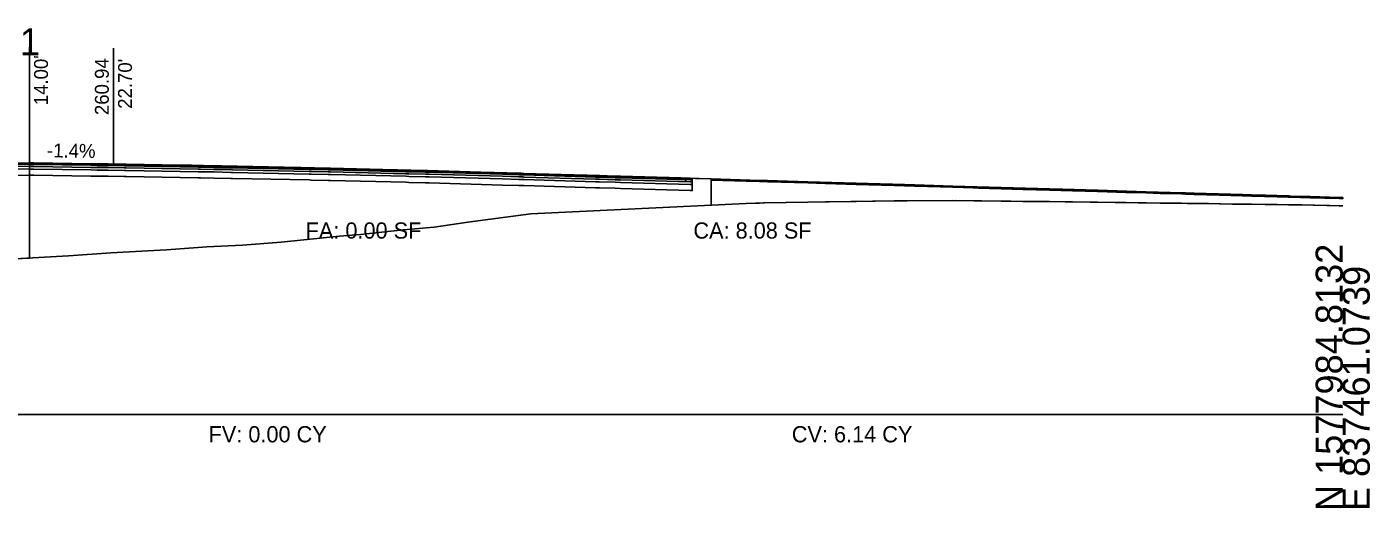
# Model space of a CAD drawing. Extents: x -26 to 6303, y -16 to 9563.
# Drawn here: x 2163.7 to 2302.8, y 3490.3 to 3540.1 of the extents above; entities that cross this region are included whole.
import ezdxf

# ---------------------------------------------------------------- set-up
doc = ezdxf.new("R2010")
doc.units = 0
for name, color, linetype in [('ASPHALT_19MM1', 7, 'Continuous'), ('ASPHALT_9_5MM1', 7, 'Continuous'), ('CONST_DCH', 7, 'Continuous'), ('CONST_LV3', 7, 'Continuous'), ('Default', 7, 'Continuous'), ('DTM_P_FINISHED_GRADE', 7, 'Continuous'), ('DTM_P_FINISHED_GRADE2', 7, 'Continuous'), ('DTM_X_GROUND', 7, 'Continuous'), ('TRANS_EOP_PAVED', 7, 'Continuous'), ('TRANS_PAVED_SHOULDERS', 7, 'Continuous'), ('XS_CELL', 7, 'Continuous'), ('XS_M_SHAPES_EARTHWORK', 7, 'Continuous'), ('XS_P_ASPHALT', 7, 'Continuous'), ('XS_P_GROUND', 7, 'Continuous'), ('XS_P_SUBGRADE_GRANULAR', 7, 'Continuous'), ('XS_P_SUBGRADE_LEVELING', 7, 'Continuous'), ('XS_P_SUBGRADE_MILLING', 7, 'Continuous'), ('XS_P_TX_CLEARZONE', 7, 'Continuous'), ('XS_P_TX_FS_BS', 7, 'Continuous'), ('XS_SHEET_EW_TX_AREA', 7, 'Continuous'), ('XS_SHEET_EW_TX_VOLUME', 7, 'Continuous')]:
    doc.layers.add(name, color=color, linetype=linetype)

msp = doc.modelspace()

# ---------------------------------------------------------------- linework, layer by layer
at = {"layer": 'ASPHALT_19MM1'}
for points in [[(2136, 3524.77), (2136, 3524.67), (2140.93, 3524.81), (2150, 3525.06), (2154.93, 3525.2), (2164, 3525.46), (2164, 3525.55), (2164, 3525.73), (2154.93, 3525.47), (2150, 3525.34), (2140.93, 3525.08), (2136, 3524.94), (2136, 3524.77)], [(2181.71, 3525.42), (2183.08, 3525.39), (2184.87, 3525.36), (2185.03, 3525.35), (2192.97, 3525.18), (2193.17, 3525.18), (2194.93, 3525.14), (2195.18, 3525.13), (2202.98, 3524.94), (2203.28, 3524.93), (2205.01, 3524.89), (2205.38, 3524.88), (2212.99, 3524.67), (2214.67, 3524.62), (2215.11, 3524.61), (2215.2, 3524.6), (2222.62, 3524.39), (2223.02, 3524.37), (2224.66, 3524.32), (2225.22, 3524.31), (2232.44, 3524.09), (2232.64, 3524.09), (2232.64, 3523.82), (2232.44, 3523.82), (2225.22, 3524.04), (2224.66, 3524.05), (2223.02, 3524.1), (2222.62, 3524.11), (2215.2, 3524.33), (2215.11, 3524.34), (2214.67, 3524.35), (2212.99, 3524.4), (2205.38, 3524.61), (2205.01, 3524.62), (2203.28, 3524.66), (2202.98, 3524.67), (2195.18, 3524.86), (2194.93, 3524.87), (2193.17, 3524.91), (2192.97, 3524.91), (2185.03, 3525.08), (2184.87, 3525.08), (2183.08, 3525.12), (2181.71, 3525.14), (2181.6, 3525.15), (2181.58, 3525.15), (2181.57, 3525.15), (2181.46, 3525.15), (2174.01, 3525.28), (2173.88, 3525.28), (2173.82, 3525.28), (2172.16, 3525.3), (2171.88, 3525.31), (2171.74, 3525.31), (2171.01, 3525.32), (2170.35, 3525.33), (2164.45, 3525.41), (2164.42, 3525.41), (2164, 3525.42), (2164, 3525.69), (2164.42, 3525.68), (2164.45, 3525.68), (2170.35, 3525.6), (2171.01, 3525.59), (2171.74, 3525.58), (2171.88, 3525.58), (2172.16, 3525.57), (2173.82, 3525.55), (2173.88, 3525.55), (2174.01, 3525.55), (2181.46, 3525.42), (2181.57, 3525.42), (2181.58, 3525.42), (2181.6, 3525.42), (2181.71, 3525.42)]]:
    msp.add_lwpolyline(points, dxfattribs=at)
at = {"layer": 'ASPHALT_9_5MM1'}
for points in [[(2136, 3525.2), (2136, 3525.15), (2140.93, 3525.29), (2150, 3525.54), (2154.93, 3525.68), (2164, 3525.94), (2164, 3525.98), (2164, 3526.06), (2154.93, 3525.81), (2150, 3525.67), (2140.93, 3525.41), (2136, 3525.28), (2136, 3525.2)], [(2181.71, 3525.75), (2183.08, 3525.72), (2184.87, 3525.69), (2185.03, 3525.68), (2192.97, 3525.52), (2193.17, 3525.51), (2194.93, 3525.47), (2195.18, 3525.47), (2202.98, 3525.28), (2203.28, 3525.27), (2205.01, 3525.23), (2205.38, 3525.21), (2212.99, 3525), (2214.67, 3524.95), (2215.11, 3524.94), (2215.2, 3524.94), (2222.62, 3524.72), (2223.02, 3524.71), (2224.66, 3524.66), (2225.22, 3524.64), (2232.44, 3524.43), (2232.64, 3524.42), (2232.64, 3524.3), (2232.44, 3524.3), (2225.22, 3524.51), (2224.66, 3524.53), (2223.02, 3524.58), (2222.62, 3524.59), (2215.2, 3524.81), (2215.11, 3524.82), (2214.67, 3524.83), (2212.99, 3524.88), (2205.38, 3525.09), (2205.01, 3525.1), (2203.28, 3525.14), (2202.98, 3525.15), (2195.18, 3525.34), (2194.93, 3525.35), (2193.17, 3525.39), (2192.97, 3525.39), (2185.03, 3525.56), (2184.87, 3525.56), (2183.08, 3525.6), (2181.71, 3525.62), (2181.6, 3525.63), (2181.58, 3525.63), (2181.57, 3525.63), (2181.46, 3525.63), (2174.01, 3525.76), (2173.88, 3525.76), (2173.82, 3525.76), (2172.16, 3525.78), (2171.88, 3525.79), (2171.74, 3525.79), (2171.01, 3525.8), (2170.35, 3525.81), (2164.45, 3525.89), (2164.42, 3525.89), (2164, 3525.9), (2164, 3526.02), (2164.42, 3526.02), (2164.45, 3526.01), (2170.35, 3525.93), (2171.01, 3525.92), (2171.74, 3525.91), (2171.88, 3525.91), (2172.16, 3525.91), (2173.82, 3525.88), (2173.88, 3525.88), (2174.01, 3525.88), (2181.46, 3525.75), (2181.57, 3525.75), (2181.58, 3525.75), (2181.6, 3525.75), (2181.71, 3525.75)]]:
    msp.add_lwpolyline(points, dxfattribs=at)
at = {"layer": 'CONST_LV3'}
for points in [[(2172.7, 3525.94), (2165.84, 3526.03), (2164, 3526.06), (2161.2, 3525.98), (2150, 3525.67)], [(2181.71, 3525.79), (2183.08, 3525.76), (2184.87, 3525.73), (2185.03, 3525.72), (2192.97, 3525.56), (2193.17, 3525.55), (2194.93, 3525.52), (2195.18, 3525.51), (2202.98, 3525.32), (2203.28, 3525.31), (2205.01, 3525.27), (2205.38, 3525.25), (2212.99, 3525.04), (2214.67, 3525), (2215.11, 3524.98), (2215.2, 3524.98), (2222.62, 3524.76), (2223.02, 3524.75), (2224.66, 3524.7), (2225.22, 3524.68), (2232.44, 3524.47), (2232.64, 3524.46), (2232.64, 3523.19), (2232.44, 3523.2), (2225.22, 3523.41), (2224.66, 3523.43), (2223.02, 3523.47), (2222.62, 3523.49), (2215.2, 3523.71), (2215.11, 3523.71), (2214.67, 3523.72), (2212.99, 3523.77), (2205.38, 3523.98), (2205.01, 3523.99), (2203.28, 3524.04), (2202.98, 3524.05), (2195.18, 3524.24), (2194.93, 3524.24), (2193.17, 3524.28), (2192.97, 3524.29), (2185.03, 3524.45), (2184.87, 3524.46), (2183.08, 3524.49), (2181.71, 3524.52), (2181.6, 3524.52), (2181.58, 3524.52), (2181.57, 3524.52), (2181.46, 3524.52), (2174.01, 3524.65), (2173.88, 3524.65), (2173.82, 3524.65), (2172.16, 3524.68), (2171.88, 3524.68), (2171.74, 3524.68), (2171.01, 3524.69), (2170.35, 3524.7), (2164.45, 3524.78), (2164.42, 3524.78), (2164, 3524.79), (2164, 3526.06), (2164.42, 3526.06), (2164.45, 3526.06), (2170.35, 3525.97), (2171.01, 3525.96), (2171.74, 3525.95), (2171.88, 3525.95), (2172.16, 3525.95), (2173.82, 3525.92), (2173.88, 3525.92), (2174.01, 3525.92), (2181.46, 3525.79), (2181.57, 3525.79), (2181.58, 3525.79), (2181.6, 3525.79), (2181.71, 3525.79)], [(2289.63, 3522.78), (2284.63, 3522.92), (2279.63, 3523.07), (2274.63, 3523.22), (2269.62, 3523.37), (2264.62, 3523.52), (2259.62, 3523.66), (2254.62, 3523.81), (2249.61, 3523.96), (2244.61, 3524.11), (2239.61, 3524.25), (2234.61, 3524.4), (2233.35, 3524.44), (2232.93, 3524.45)]]:
    msp.add_lwpolyline(points, dxfattribs=at)
at = {"layer": 'Default'}
msp.add_lwpolyline([(2172.7, 3525.94), (2173.84, 3525.92), (2173.9, 3525.92), (2174.02, 3525.92), (2178.59, 3525.84), (2180.56, 3525.81), (2180.66, 3525.81), (2180.67, 3525.81), (2180.77, 3525.81), (2183.3, 3525.76), (2183.88, 3525.75), (2190.38, 3525.61), (2192.04, 3525.58), (2192.13, 3525.57), (2194.93, 3525.52), (2194.93, 3525.52), (2194.96, 3525.51), (2194.98, 3525.51), (2195.07, 3525.51), (2195.18, 3525.51), (2201.95, 3525.34), (2201.99, 3525.34), (2202.02, 3525.34), (2202.13, 3525.34), (2204.88, 3525.27), (2205, 3525.27), (2205.01, 3525.27), (2205.05, 3525.26), (2205.1, 3525.26), (2205.23, 3525.26), (2211.85, 3525.07), (2211.99, 3525.07), (2211.99, 3525.07), (2211.99, 3525.07), (2212.03, 3525.07), (2212.03, 3525.07), (2212.07, 3525.07), (2212.11, 3525.07), (2214.79, 3524.99), (2214.91, 3524.99), (2215.11, 3524.98), (2215.11, 3524.98), (2215.2, 3524.98), (2221.65, 3524.79), (2221.67, 3524.79), (2221.69, 3524.79), (2221.77, 3524.78), (2222.05, 3524.77), (2222.05, 3524.77), (2224.66, 3524.7), (2224.74, 3524.69), (2224.83, 3524.69), (2225.02, 3524.69), (2225.21, 3524.68), (2231.49, 3524.5), (2231.49, 3524.5), (2231.5, 3524.5), (2231.7, 3524.49), (2232.04, 3524.13)], dxfattribs=at)
at = {"layer": 'DTM_P_FINISHED_GRADE'}
msp.add_lwpolyline([(2164, 3526.06), (2164.42, 3526.06), (2164.45, 3526.06), (2170.35, 3525.97), (2171.01, 3525.96), (2171.74, 3525.95), (2171.88, 3525.95), (2172.16, 3525.95), (2173.82, 3525.92), (2173.88, 3525.92), (2174.01, 3525.92), (2181.46, 3525.79), (2181.57, 3525.79), (2181.58, 3525.79), (2181.6, 3525.79), (2181.71, 3525.79), (2183.08, 3525.76), (2184.87, 3525.73), (2185.03, 3525.72), (2192.97, 3525.56), (2193.17, 3525.55), (2194.93, 3525.52), (2195.18, 3525.51), (2202.98, 3525.32), (2203.28, 3525.31), (2205.01, 3525.27), (2205.38, 3525.25), (2212.99, 3525.04), (2214.67, 3525), (2215.11, 3524.98), (2215.2, 3524.98), (2222.62, 3524.76), (2223.02, 3524.75), (2224.66, 3524.7), (2225.22, 3524.68), (2232.44, 3524.47), (2232.64, 3524.46)], dxfattribs=at)
at = {"layer": 'DTM_P_FINISHED_GRADE2'}
msp.add_lwpolyline([(2160.54, 3525.96), (2164, 3526.06), (2164.42, 3526.06), (2164.45, 3526.06), (2170.35, 3525.97), (2171.01, 3525.96), (2171.88, 3525.95), (2172.16, 3525.95), (2173.82, 3525.92), (2173.88, 3525.92), (2174.01, 3525.92), (2181.46, 3525.79), (2181.58, 3525.79), (2181.6, 3525.79), (2181.71, 3525.79), (2183.08, 3525.76), (2184.87, 3525.73), (2185.03, 3525.72), (2192.97, 3525.56), (2193.17, 3525.55), (2194.93, 3525.52), (2195.18, 3525.51), (2202.98, 3525.32), (2203.28, 3525.31), (2205.01, 3525.27), (2205.38, 3525.25), (2212.99, 3525.04), (2213.03, 3525.04), (2214.71, 3524.99), (2215.11, 3524.98), (2215.2, 3524.98), (2222.62, 3524.76), (2223.02, 3524.75), (2224.66, 3524.7), (2225.22, 3524.68), (2225.92, 3524.66), (2233.04, 3524.45), (2234.61, 3524.4), (2235.37, 3524.38), (2239.61, 3524.25), (2240.44, 3524.23), (2244.61, 3524.11), (2245.52, 3524.08), (2249.61, 3523.96), (2250.6, 3523.93), (2254.62, 3523.81), (2255.69, 3523.78), (2259.62, 3523.66), (2260.78, 3523.63), (2264.62, 3523.52), (2265.88, 3523.48), (2269.62, 3523.37), (2270.99, 3523.33), (2274.62, 3523.22), (2274.62, 3523.22), (2274.63, 3523.22), (2276.11, 3523.18), (2279.63, 3523.07), (2280.8, 3523.04), (2283.31, 3522.96), (2283.74, 3522.95), (2284.63, 3522.92), (2286.38, 3522.87), (2289.63, 3522.78), (2289.97, 3522.77), (2290.57, 3522.75), (2292.02, 3522.71), (2294.38, 3522.64), (2294.48, 3522.63), (2294.63, 3522.63), (2296.64, 3522.57), (2299.64, 3522.48), (2300, 3522.47)], dxfattribs=at)
at = {"layer": 'DTM_X_GROUND'}
msp.add_lwpolyline([(2162.49, 3516.12), (2168.04, 3516.42), (2172.43, 3516.75), (2178.19, 3517.05), (2182.37, 3517.36), (2186.08, 3517.55), (2190.07, 3517.85), (2196.11, 3518.47), (2198.27, 3518.66), (2202.7, 3519.12), (2205.91, 3519.4), (2209.4, 3519.91), (2215.91, 3520.79), (2238.24, 3521.84), (2240.11, 3521.93), (2253.55, 3522.12), (2259.91, 3522.18), (2262.13, 3522.14), (2262.59, 3522.13), (2268.67, 3522.06), (2276.42, 3521.97), (2278.81, 3521.93), (2286.11, 3521.84), (2288.57, 3521.8), (2295.32, 3521.72), (2298.64, 3521.64), (2300, 3521.61)], dxfattribs=at)
at = {"layer": 'TRANS_PAVED_SHOULDERS'}
for points in [[(2136, 3525.02), (2136, 3524.94), (2140.93, 3525.08), (2150, 3525.34), (2154.93, 3525.47), (2164, 3525.73), (2164, 3525.8), (2164, 3525.94), (2154.93, 3525.68), (2150, 3525.54), (2140.93, 3525.29), (2136, 3525.15), (2136, 3525.02)], [(2181.71, 3525.62), (2183.08, 3525.6), (2184.87, 3525.56), (2185.03, 3525.56), (2192.97, 3525.39), (2193.17, 3525.39), (2194.93, 3525.35), (2195.18, 3525.34), (2202.98, 3525.15), (2203.28, 3525.14), (2205.01, 3525.1), (2205.38, 3525.09), (2212.99, 3524.88), (2214.67, 3524.83), (2215.11, 3524.82), (2215.2, 3524.81), (2222.62, 3524.59), (2223.02, 3524.58), (2224.66, 3524.53), (2225.22, 3524.51), (2232.44, 3524.3), (2232.64, 3524.3), (2232.64, 3524.09), (2232.44, 3524.09), (2225.22, 3524.31), (2224.66, 3524.32), (2223.02, 3524.37), (2222.62, 3524.39), (2215.2, 3524.6), (2215.11, 3524.61), (2214.67, 3524.62), (2212.99, 3524.67), (2205.38, 3524.88), (2205.01, 3524.89), (2203.28, 3524.93), (2202.98, 3524.94), (2195.18, 3525.13), (2194.93, 3525.14), (2193.17, 3525.18), (2192.97, 3525.18), (2185.03, 3525.35), (2184.87, 3525.36), (2183.08, 3525.39), (2181.71, 3525.42), (2181.6, 3525.42), (2181.58, 3525.42), (2181.57, 3525.42), (2181.46, 3525.42), (2174.01, 3525.55), (2173.88, 3525.55), (2173.82, 3525.55), (2172.16, 3525.57), (2171.88, 3525.58), (2171.74, 3525.58), (2171.01, 3525.59), (2170.35, 3525.6), (2164.45, 3525.68), (2164.42, 3525.68), (2164, 3525.69), (2164, 3525.9), (2164.42, 3525.89), (2164.45, 3525.89), (2170.35, 3525.81), (2171.01, 3525.8), (2171.74, 3525.79), (2171.88, 3525.79), (2172.16, 3525.78), (2173.82, 3525.76), (2173.88, 3525.76), (2174.01, 3525.76), (2181.46, 3525.63), (2181.57, 3525.63), (2181.58, 3525.63), (2181.6, 3525.63), (2181.71, 3525.62)]]:
    msp.add_lwpolyline(points, dxfattribs=at)
at = {"layer": 'XS_CELL'}
msp.add_line((2150, 3500), (2300, 3500), dxfattribs=at)
at = {"layer": 'XS_M_SHAPES_EARTHWORK'}
msp.add_lwpolyline([(2162.49, 3516.12), (2164, 3516.2), (2164, 3525.46), (2154.93, 3525.2)], dxfattribs=at)
at = {"layer": 'XS_P_ASPHALT'}
for points in [[(2164, 3526.06), (2164.42, 3526.06), (2164.45, 3526.06), (2170.35, 3525.97), (2171.01, 3525.96), (2171.74, 3525.95), (2171.88, 3525.95), (2172.16, 3525.95), (2173.82, 3525.92), (2173.88, 3525.92), (2174.01, 3525.92), (2181.46, 3525.79), (2181.57, 3525.79), (2181.58, 3525.79), (2181.6, 3525.79), (2181.71, 3525.79), (2183.08, 3525.76), (2184.87, 3525.73), (2185.03, 3525.72), (2192.97, 3525.56), (2193.17, 3525.55), (2194.93, 3525.52), (2195.18, 3525.51), (2202.98, 3525.32), (2203.28, 3525.31), (2205.01, 3525.27), (2205.38, 3525.25), (2212.99, 3525.04), (2214.67, 3525), (2215.11, 3524.98), (2215.2, 3524.98), (2222.62, 3524.76), (2223.02, 3524.75), (2224.66, 3524.7), (2225.22, 3524.68), (2232.44, 3524.47), (2232.64, 3524.46)], [(2300, 3522.47), (2300, 3522.35), (2300, 3522.35), (2299.64, 3522.36), (2299.64, 3522.36), (2296.64, 3522.44), (2296.64, 3522.44), (2294.63, 3522.5), (2294.63, 3522.5), (2294.48, 3522.51), (2294.48, 3522.51), (2294.38, 3522.51), (2294.38, 3522.51), (2292.02, 3522.58), (2292.02, 3522.58), (2290.57, 3522.62), (2290.57, 3522.62), (2289.97, 3522.64), (2289.97, 3522.64), (2289.63, 3522.65), (2289.63, 3522.65), (2286.38, 3522.75), (2286.38, 3522.75), (2284.63, 3522.8), (2284.63, 3522.8), (2283.74, 3522.83), (2283.74, 3522.83), (2283.31, 3522.84), (2283.31, 3522.84), (2280.8, 3522.91), (2280.8, 3522.91), (2279.63, 3522.95), (2279.63, 3522.95), (2276.11, 3523.05), (2276.11, 3523.05), (2274.63, 3523.1), (2274.63, 3523.1), (2274.62, 3523.1), (2274.62, 3523.1), (2274.62, 3523.1), (2274.62, 3523.1), (2270.99, 3523.2), (2270.99, 3523.2), (2269.62, 3523.24), (2269.62, 3523.24), (2265.88, 3523.35), (2265.88, 3523.35), (2264.62, 3523.39), (2264.62, 3523.39), (2260.78, 3523.5), (2260.78, 3523.5), (2259.62, 3523.54), (2259.62, 3523.54), (2255.69, 3523.65), (2255.69, 3523.65), (2254.62, 3523.69), (2254.62, 3523.69), (2250.6, 3523.81), (2250.6, 3523.81), (2249.61, 3523.83), (2249.61, 3523.83), (2245.52, 3523.96), (2245.52, 3523.96), (2244.61, 3523.98), (2244.61, 3523.98), (2240.44, 3524.11), (2240.44, 3524.11), (2239.61, 3524.13), (2239.61, 3524.13), (2235.37, 3524.26), (2235.37, 3524.26), (2234.61, 3524.28), (2234.61, 3524.28), (2234.61, 3524.3), (2234.61, 3524.3), (2234.61, 3524.4), (2234.61, 3524.4), (2235.37, 3524.38), (2235.37, 3524.38), (2239.61, 3524.25), (2239.61, 3524.25), (2240.44, 3524.23), (2240.44, 3524.23), (2244.61, 3524.11), (2244.61, 3524.11), (2245.52, 3524.08), (2245.52, 3524.08), (2249.61, 3523.96), (2249.61, 3523.96), (2250.6, 3523.93), (2250.6, 3523.93), (2254.62, 3523.81), (2254.62, 3523.81), (2255.69, 3523.78), (2255.69, 3523.78), (2259.62, 3523.66), (2259.62, 3523.66), (2260.78, 3523.63), (2260.78, 3523.63), (2264.62, 3523.52), (2264.62, 3523.52), (2265.88, 3523.48), (2265.88, 3523.48), (2269.62, 3523.37), (2269.62, 3523.37), (2270.99, 3523.33), (2270.99, 3523.33), (2274.62, 3523.22), (2274.62, 3523.22), (2274.62, 3523.22), (2274.62, 3523.22), (2274.63, 3523.22), (2274.63, 3523.22), (2276.11, 3523.18), (2276.11, 3523.18), (2279.63, 3523.07), (2279.63, 3523.07), (2280.8, 3523.04), (2280.8, 3523.04), (2283.31, 3522.96), (2283.31, 3522.96), (2283.74, 3522.95), (2283.74, 3522.95), (2284.63, 3522.92), (2284.63, 3522.92), (2286.38, 3522.87), (2286.38, 3522.87), (2289.63, 3522.78), (2289.63, 3522.78), (2289.97, 3522.77), (2289.97, 3522.77), (2290.57, 3522.75), (2290.57, 3522.75), (2292.02, 3522.71), (2292.02, 3522.71), (2294.38, 3522.64), (2294.38, 3522.64), (2294.48, 3522.63), (2294.48, 3522.63), (2294.63, 3522.63), (2294.63, 3522.63), (2296.64, 3522.57), (2296.64, 3522.57), (2299.64, 3522.48), (2299.64, 3522.48), (2300, 3522.47)]]:
    msp.add_lwpolyline(points, dxfattribs=at)
at = {"layer": 'XS_P_GROUND'}
msp.add_lwpolyline([(2172.7, 3525.94), (2172.7, 3525.94), (2172.7, 3525.94), (2172.7, 3525.94)], dxfattribs=at)
at = {"layer": 'XS_P_SUBGRADE_GRANULAR'}
for points in [[(2164, 3524.79), (2154.93, 3524.54), (2150, 3524.4)], [(2164, 3524.79), (2164.42, 3524.78), (2164.45, 3524.78), (2170.35, 3524.7), (2171.01, 3524.69), (2171.74, 3524.68), (2171.88, 3524.68), (2172.16, 3524.68), (2173.82, 3524.65), (2173.88, 3524.65), (2174.01, 3524.65), (2181.46, 3524.52), (2181.57, 3524.52), (2181.58, 3524.52), (2181.6, 3524.52), (2181.71, 3524.52), (2183.08, 3524.49), (2184.87, 3524.46), (2185.03, 3524.45), (2192.97, 3524.29), (2193.17, 3524.28), (2194.93, 3524.24), (2195.18, 3524.24), (2202.98, 3524.05), (2203.28, 3524.04), (2205.01, 3523.99), (2205.38, 3523.98), (2212.99, 3523.77), (2214.67, 3523.72), (2215.11, 3523.71), (2215.2, 3523.71), (2222.62, 3523.49), (2223.02, 3523.47), (2224.66, 3523.43), (2225.22, 3523.41), (2232.44, 3523.2), (2232.64, 3523.19)]]:
    msp.add_lwpolyline(points, dxfattribs=at)
at = {"layer": 'XS_P_SUBGRADE_LEVELING'}
msp.add_lwpolyline([(2300, 3521.61), (2299.64, 3521.62), (2295.81, 3521.71), (2294.63, 3521.73), (2294.57, 3521.73), (2294.38, 3521.73), (2293.21, 3521.75), (2290.57, 3521.78), (2290.11, 3521.78), (2289.63, 3521.79), (2287.23, 3521.83), (2284.63, 3521.86), (2283.93, 3521.87), (2283.31, 3521.88), (2281.11, 3521.9), (2279.63, 3521.92), (2277.53, 3521.95), (2274.63, 3521.99), (2274.62, 3521.99), (2274.62, 3521.99), (2272.02, 3522.02), (2269.62, 3522.05), (2266.86, 3522.08), (2264.62, 3522.11), (2262.27, 3522.14), (2261.8, 3522.14), (2259.62, 3522.17), (2254.91, 3522.13), (2254.62, 3522.13), (2253.55, 3522.12), (2249.61, 3522.06), (2246.44, 3522.02), (2244.61, 3521.99), (2240.02, 3521.91), (2239.61, 3521.9), (2238.24, 3521.84), (2234.61, 3521.67), (2234.61, 3522.61), (2234.61, 3524.28), (2238.24, 3524.17), (2239.61, 3524.13), (2240.02, 3524.12), (2244.61, 3523.98), (2246.44, 3523.93), (2249.61, 3523.83), (2253.55, 3523.72), (2254.62, 3523.69), (2254.91, 3523.68), (2259.62, 3523.54), (2261.8, 3523.47), (2262.27, 3523.46), (2264.62, 3523.39), (2266.86, 3523.32), (2269.62, 3523.24), (2272.02, 3523.17), (2274.62, 3523.1), (2274.62, 3523.1), (2274.63, 3523.1), (2277.53, 3523.01), (2279.63, 3522.95), (2281.11, 3522.9), (2283.31, 3522.84), (2283.93, 3522.82), (2284.63, 3522.8), (2287.23, 3522.72), (2289.63, 3522.65), (2290.11, 3522.64), (2290.57, 3522.62), (2293.21, 3522.55), (2294.38, 3522.51), (2294.57, 3522.51), (2294.63, 3522.5), (2295.81, 3522.47), (2299.64, 3522.36), (2300, 3522.35)], dxfattribs=at)
at = {"layer": 'XS_P_SUBGRADE_MILLING'}
msp.add_lwpolyline([(2300, 3521.61), (2299.64, 3521.62), (2295.81, 3521.71), (2294.63, 3521.73), (2294.57, 3521.73), (2294.38, 3521.73), (2293.21, 3521.75), (2290.57, 3521.78), (2290.11, 3521.78), (2289.63, 3521.79), (2287.23, 3521.83), (2284.63, 3521.86), (2283.93, 3521.87), (2283.31, 3521.88), (2281.11, 3521.9), (2279.63, 3521.92), (2277.53, 3521.95), (2274.63, 3521.99), (2274.62, 3521.99), (2274.62, 3521.99), (2272.02, 3522.02), (2269.62, 3522.05), (2266.86, 3522.08), (2264.62, 3522.11), (2262.27, 3522.14), (2261.8, 3522.14), (2259.62, 3522.17), (2254.91, 3522.13), (2254.62, 3522.13), (2253.55, 3522.12), (2249.61, 3522.06), (2246.44, 3522.02), (2244.61, 3521.99), (2240.02, 3521.91), (2239.61, 3521.9), (2238.24, 3521.84), (2234.61, 3521.67), (2234.61, 3521.67), (2234.61, 3521.67), (2238.24, 3521.84), (2239.61, 3521.9), (2240.02, 3521.91), (2244.61, 3521.99), (2246.44, 3522.02), (2249.61, 3522.06), (2253.55, 3522.12), (2254.62, 3522.13), (2254.91, 3522.13), (2259.62, 3522.17), (2261.8, 3522.14), (2262.27, 3522.14), (2264.62, 3522.11), (2266.86, 3522.08), (2269.62, 3522.05), (2272.02, 3522.02), (2274.62, 3521.99), (2274.62, 3521.99), (2274.63, 3521.99), (2277.53, 3521.95), (2279.63, 3521.92), (2281.11, 3521.9), (2283.31, 3521.88), (2283.93, 3521.87), (2284.63, 3521.86), (2287.23, 3521.83), (2289.63, 3521.79), (2290.11, 3521.78), (2290.57, 3521.78), (2293.21, 3521.75), (2294.38, 3521.73), (2294.57, 3521.73), (2294.63, 3521.73), (2295.81, 3521.71), (2299.64, 3521.62), (2300, 3521.61)], dxfattribs=at)
at = {"layer": 'XS_P_TX_CLEARZONE'}
for p, q in [((2164, 3526.06), (2164, 3538.06)), ((2172.7, 3525.94), (2172.7, 3537.94))]:
    msp.add_line(p, q, dxfattribs=at)

# ---------------------------------------------------------------- texts
at = {"layer": 'CONST_DCH'}
msp.add_text('X', height=0.24, dxfattribs=at).set_placement((2163.92, 3525.94))
at = {"layer": 'TRANS_EOP_PAVED'}
msp.add_text('X', height=0.24, dxfattribs=at).set_placement((2172.63, 3525.82))
at = {"layer": 'XS_CELL'}
msp.add_text('1243+41.00 / 1', height=2.8, dxfattribs=at).set_placement((2140, 3537.2))
for s, p in [('N 1577984.8132', (2300, 3490)), ('E 837461.0739', (2302.8, 3490))]:
    msp.add_text(s, height=2.8, rotation=90, dxfattribs=at).set_placement(p)
at = {"layer": 'XS_P_TX_CLEARZONE'}
for s, p in [("14.00'", (2165.92, 3532.03)), ('260.94', (2172.22, 3531.01)), ("22.70'", (2174.62, 3531.66))]:
    msp.add_text(s, height=1.44, rotation=90, dxfattribs=at).set_placement(p)
at = {"layer": 'XS_P_TX_FS_BS'}
msp.add_text('-1.4%', height=1.44, rotation=359.2121, dxfattribs=at).set_placement((2165.81, 3526.64))
at = {"layer": 'XS_SHEET_EW_TX_AREA'}
for s, p in [('FA: 0.00 SF', (2192.6, 3518.22)), ('CA: 8.08 SF', (2232.76, 3518.22))]:
    msp.add_text(s, height=1.68, dxfattribs=at).set_placement(p)
at = {"layer": 'XS_SHEET_EW_TX_VOLUME'}
for s, p in [('FV: 0.00 CY', (2182.55, 3497.12)), ('CV: 6.14 CY', (2242.95, 3497.12))]:
    msp.add_text(s, height=1.68, dxfattribs=at).set_placement(p)

doc.saveas('drawing.dxf')
